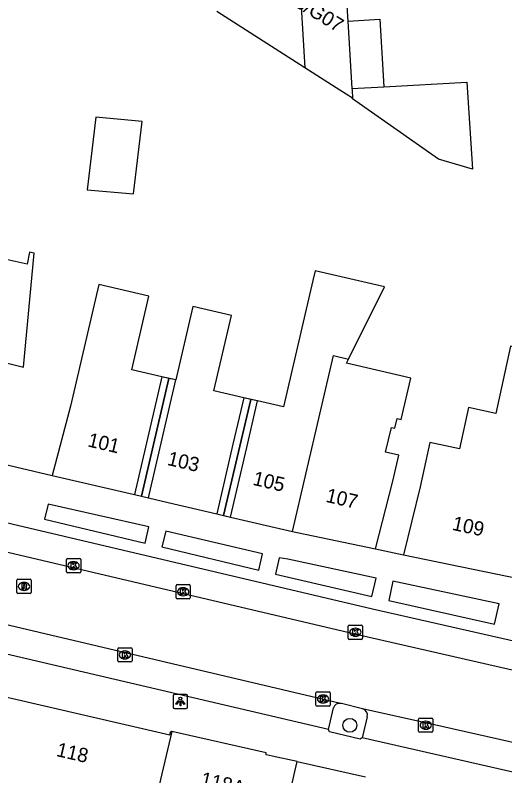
# Model space of a CAD drawing. Extents: x 159888 to 160757, y 384031 to 384746.
# Drawn here: x 160309.4 to 160343.9, y 384451.7 to 384505.3 of the extents above; entities that cross this region are included whole.
import ezdxf

# ---------------------------------------------------------------- set-up
doc = ezdxf.new("R2010")
doc.units = 0
for name, color, linetype in [('IMGEO_Boom', 7, 'Continuous'), ('IMGEO_Erf', 7, 'Continuous'), ('IMGEO_Kolk', 7, 'Continuous'), ('IMGEO_Lichtpunt', 7, 'Continuous'), ('IMGEO_Pand', 7, 'Continuous'), ('IMGEO_Pand_nummerreeks', 7, 'Continuous'), ('IMGEO_Pand_overbouw', 7, 'Continuous'), ('IMGEO_Parkeervlak_open', 7, 'Continuous'), ('IMGEO_Rijbaan_lokaal_open', 7, 'Continuous'), ('IMGEO_Rioolput', 7, 'Continuous'), ('IMGEO_Voetpad_open', 7, 'Continuous')]:
    doc.layers.add(name, color=color, linetype=linetype)

msp = doc.modelspace()

# ---------------------------------------------------------------- linework, layer by layer
at = {"layer": 'IMGEO_Boom'}
msp.add_circle((160332.99, 384455.291), 0.489, dxfattribs=at)
at = {"layer": 'IMGEO_Erf'}
for points in [[(160320.729, 384479.597), (160319.752, 384479.824)], [(160326.491, 384478.118), (160325.517, 384478.344)]]:
    msp.add_lwpolyline(points, dxfattribs=at)
at = {"layer": 'IMGEO_Kolk'}
for p, q in [((160313.032, 384466.101), (160313.032, 384466.953)), ((160313.107, 384467.027), (160313.959, 384467.027)), ((160313.52, 384466.807), (160313.545, 384466.807)), ((160314.033, 384466.953), (160314.033, 384466.101)), ((160313.959, 384466.027), (160313.107, 384466.027)), ((160313.543, 384466.247), (160313.518, 384466.247)), ((160320.751, 384464.263), (160320.751, 384465.115)), ((160320.826, 384465.189), (160321.678, 384465.189)), ((160321.239, 384464.969), (160321.264, 384464.969)), ((160321.752, 384465.115), (160321.752, 384464.263)), ((160321.262, 384464.409), (160321.237, 384464.409)), ((160321.678, 384464.189), (160320.826, 384464.189)), ((160332.876, 384461.415), (160332.876, 384462.267)), ((160332.951, 384462.341), (160333.803, 384462.341)), ((160333.877, 384462.267), (160333.877, 384461.415)), ((160333.364, 384462.121), (160333.389, 384462.121)), ((160333.803, 384461.341), (160332.951, 384461.341)), ((160333.387, 384461.561), (160333.362, 384461.561)), ((160316.649, 384459.822), (160316.649, 384460.674)), ((160316.724, 384460.748), (160317.576, 384460.748)), ((160317.65, 384460.674), (160317.65, 384459.822)), ((160317.137, 384460.528), (160317.162, 384460.528)), ((160317.576, 384459.748), (160316.724, 384459.748)), ((160317.16, 384459.968), (160317.135, 384459.968)), ((160330.601, 384456.714), (160330.601, 384457.566)), ((160330.676, 384457.64), (160331.528, 384457.64)), ((160331.602, 384457.566), (160331.602, 384456.714)), ((160331.089, 384457.42), (160331.114, 384457.42)), ((160331.528, 384456.64), (160330.676, 384456.64)), ((160331.112, 384456.86), (160331.087, 384456.86)), ((160337.832, 384454.872), (160337.832, 384455.724)), ((160337.907, 384455.798), (160338.759, 384455.798)), ((160338.32, 384455.578), (160338.345, 384455.578)), ((160338.833, 384455.724), (160338.833, 384454.872)), ((160338.759, 384454.798), (160337.907, 384454.798)), ((160338.343, 384455.018), (160338.318, 384455.018))]:
    msp.add_line(p, q, dxfattribs=at)
for points in [[(160313.032, 384466.101), (160313.032, 384466.953)], [(160313.107, 384467.027), (160313.959, 384467.027)], [(160313.353, 384466.727), (160313.476, 384466.727), (160313.476, 384466.576), (160313.606, 384466.727), (160313.77, 384466.727), (160313.624, 384466.576), (160313.777, 384466.327), (160313.625, 384466.327), (160313.54, 384466.491), (160313.476, 384466.424), (160313.476, 384466.327), (160313.353, 384466.327), (160313.353, 384466.727)], [(160314.033, 384466.953), (160314.033, 384466.101)], [(160313.959, 384466.027), (160313.107, 384466.027)], [(160320.751, 384464.263), (160320.751, 384465.115)], [(160320.826, 384465.189), (160321.678, 384465.189)], [(160321.752, 384465.115), (160321.752, 384464.263)], [(160321.072, 384464.889), (160321.195, 384464.889), (160321.195, 384464.738), (160321.325, 384464.889), (160321.489, 384464.889), (160321.343, 384464.738), (160321.496, 384464.489), (160321.344, 384464.489), (160321.259, 384464.653), (160321.195, 384464.586), (160321.195, 384464.489), (160321.072, 384464.489), (160321.072, 384464.889)], [(160321.678, 384464.189), (160320.826, 384464.189)], [(160332.876, 384461.415), (160332.876, 384462.267)], [(160332.951, 384462.341), (160333.803, 384462.341)], [(160333.877, 384462.267), (160333.877, 384461.415)], [(160333.197, 384462.041), (160333.32, 384462.041), (160333.32, 384461.89), (160333.45, 384462.041), (160333.614, 384462.041), (160333.468, 384461.89), (160333.621, 384461.641), (160333.469, 384461.641), (160333.384, 384461.805), (160333.32, 384461.738), (160333.32, 384461.641), (160333.197, 384461.641), (160333.197, 384462.041)], [(160333.803, 384461.341), (160332.951, 384461.341)], [(160316.649, 384459.822), (160316.649, 384460.674)], [(160316.724, 384460.748), (160317.576, 384460.748)], [(160317.65, 384460.674), (160317.65, 384459.822)], [(160316.97, 384460.448), (160317.093, 384460.448), (160317.093, 384460.297), (160317.223, 384460.448), (160317.387, 384460.448), (160317.241, 384460.297), (160317.394, 384460.048), (160317.242, 384460.048), (160317.157, 384460.212), (160317.093, 384460.145), (160317.093, 384460.048), (160316.97, 384460.048), (160316.97, 384460.448)], [(160317.576, 384459.748), (160316.724, 384459.748)], [(160330.601, 384456.714), (160330.601, 384457.566)], [(160330.676, 384457.64), (160331.528, 384457.64)], [(160331.602, 384457.566), (160331.602, 384456.714)], [(160330.922, 384457.34), (160331.045, 384457.34), (160331.045, 384457.189), (160331.175, 384457.34), (160331.339, 384457.34), (160331.193, 384457.189), (160331.346, 384456.94), (160331.194, 384456.94), (160331.109, 384457.104), (160331.045, 384457.037), (160331.045, 384456.94), (160330.922, 384456.94), (160330.922, 384457.34)], [(160331.528, 384456.64), (160330.676, 384456.64)], [(160337.832, 384454.872), (160337.832, 384455.724)], [(160337.907, 384455.798), (160338.759, 384455.798)], [(160338.153, 384455.498), (160338.276, 384455.498), (160338.276, 384455.347), (160338.406, 384455.498), (160338.57, 384455.498), (160338.424, 384455.347), (160338.577, 384455.098), (160338.425, 384455.098), (160338.34, 384455.262), (160338.276, 384455.195), (160338.276, 384455.098), (160338.153, 384455.098), (160338.153, 384455.498)], [(160338.833, 384455.724), (160338.833, 384454.872)], [(160338.759, 384454.798), (160337.907, 384454.798)]]:
    msp.add_lwpolyline(points, dxfattribs=at)
for centre, start, end in [((160313.109, 384466.951), 91.552, 178.448), ((160313.109, 384466.951), 91.552, 178.448), ((160313.957, 384466.951), 1.552, 88.448), ((160313.957, 384466.951), 1.552, 88.448), ((160313.109, 384466.103), 181.552, 268.448), ((160313.109, 384466.103), 181.552, 268.448), ((160313.957, 384466.103), 271.552, 358.448), ((160313.957, 384466.103), 271.552, 358.448), ((160320.828, 384465.113), 91.552, 178.448), ((160320.828, 384465.113), 91.552, 178.448), ((160321.676, 384465.113), 1.552, 88.448), ((160321.676, 384465.113), 1.552, 88.448), ((160320.828, 384464.265), 181.552, 268.448), ((160320.828, 384464.265), 181.552, 268.448), ((160321.676, 384464.265), 271.552, 358.448), ((160321.676, 384464.265), 271.552, 358.448), ((160332.953, 384462.265), 91.552, 178.448), ((160332.953, 384462.265), 91.552, 178.448), ((160333.801, 384462.265), 1.552, 88.448), ((160333.801, 384462.265), 1.552, 88.448), ((160332.953, 384461.417), 181.552, 268.448), ((160332.953, 384461.417), 181.552, 268.448), ((160333.801, 384461.417), 271.552, 358.448), ((160333.801, 384461.417), 271.552, 358.448), ((160316.726, 384460.672), 91.552, 178.448), ((160316.726, 384460.672), 91.552, 178.448), ((160317.574, 384460.672), 1.552, 88.448), ((160317.574, 384460.672), 1.552, 88.448), ((160316.726, 384459.824), 181.552, 268.448), ((160316.726, 384459.824), 181.552, 268.448), ((160317.574, 384459.824), 271.552, 358.448), ((160317.574, 384459.824), 271.552, 358.448), ((160330.678, 384457.564), 91.552, 178.448), ((160330.678, 384457.564), 91.552, 178.448), ((160331.526, 384457.564), 1.552, 88.448), ((160331.526, 384457.564), 1.552, 88.448), ((160330.678, 384456.716), 181.552, 268.448), ((160330.678, 384456.716), 181.552, 268.448), ((160331.526, 384456.716), 271.552, 358.448), ((160331.526, 384456.716), 271.552, 358.448), ((160337.909, 384455.722), 91.552, 178.448), ((160337.909, 384455.722), 91.552, 178.448), ((160338.757, 384455.722), 1.552, 88.448), ((160338.757, 384455.722), 1.552, 88.448), ((160337.909, 384454.874), 181.552, 268.448), ((160337.909, 384454.874), 181.552, 268.448), ((160338.757, 384454.874), 271.552, 358.448), ((160338.757, 384454.874), 271.552, 358.448)]:
    msp.add_arc(centre, 0.0765, start, end, dxfattribs=at)
for centre, major_axis, ratio, start_param, end_param in [((160313.519, 384466.527), (-0.387, 0.002), 0.722429, 4.712389, 7.853982), ((160313.544, 384466.527), (-0.39, 0.002), 0.717154, 1.570796, 4.712389), ((160321.238, 384464.689), (-0.387, 0.002), 0.722429, 4.712389, 7.853982), ((160321.263, 384464.689), (-0.39, 0.002), 0.717154, 1.570796, 4.712389), ((160333.363, 384461.841), (-0.387, 0.002), 0.722429, 4.712389, 7.853982), ((160333.388, 384461.841), (-0.39, 0.002), 0.717154, 1.570796, 4.712389), ((160317.136, 384460.248), (-0.387, 0.002), 0.722429, 4.712389, 7.853982), ((160317.161, 384460.248), (-0.39, 0.002), 0.717154, 1.570796, 4.712389), ((160331.088, 384457.14), (-0.387, 0.002), 0.722429, 4.712389, 7.853982), ((160331.113, 384457.14), (-0.39, 0.002), 0.717154, 1.570796, 4.712389), ((160338.319, 384455.298), (-0.387, 0.002), 0.722429, 4.712389, 7.853982), ((160338.344, 384455.298), (-0.39, 0.002), 0.717154, 1.570796, 4.712389)]:
    msp.add_ellipse(centre, major_axis=major_axis, ratio=ratio, start_param=start_param, end_param=end_param, dxfattribs=at)
at = {"layer": 'IMGEO_Lichtpunt'}
for p, q in [((160321.456, 384457.468), (160320.648, 384457.468)), ((160321.456, 384457.468), (160320.648, 384457.468)), ((160320.554, 384457.373), (160320.554, 384456.566)), ((160320.554, 384457.373), (160320.554, 384456.566)), ((160321.55, 384456.566), (160321.55, 384457.373)), ((160321.55, 384456.566), (160321.55, 384457.373)), ((160320.648, 384456.472), (160321.456, 384456.472)), ((160320.648, 384456.472), (160321.456, 384456.472))]:
    msp.add_line(p, q, dxfattribs=at)
for points in [[(160320.928, 384457.037), (160320.967, 384457.009), (160320.779, 384456.747), (160320.741, 384456.774), (160320.928, 384457.037)], [(160321.03, 384456.989), (160321.077, 384456.989), (160321.077, 384456.667), (160321.03, 384456.667), (160321.03, 384456.989)], [(160321.14, 384457.009), (160321.178, 384457.036), (160321.365, 384456.774), (160321.326, 384456.746), (160321.14, 384457.009)]]:
    msp.add_lwpolyline(points, dxfattribs=at)
msp.add_circle((160321.053, 384457.171), 0.0994, dxfattribs=at)
for centre, start, end in [((160320.648, 384457.373), 90, 180), ((160320.648, 384457.373), 90, 180), ((160321.456, 384457.373), 0, 90), ((160321.456, 384457.373), 0, 90), ((160320.648, 384456.566), 180, 270), ((160320.648, 384456.566), 180, 270), ((160321.456, 384456.566), 270, 0), ((160321.456, 384456.566), 270, 360)]:
    msp.add_arc(centre, 0.0946, start, end, dxfattribs=at)
at = {"layer": 'IMGEO_Pand'}
for points in [[(160332.338, 384512.734), (160332.835, 384504.845)], [(160329.154, 384512.544), (160329.809, 384501.573)], [(160329.809, 384501.573), (160323.63, 384505.519)], [(160332.835, 384504.845), (160335.088, 384504.987), (160335.387, 384500.238)], [(160332.835, 384504.845), (160333.134, 384500.117)], [(160333.177, 384499.422), (160332.272, 384500), (160329.809, 384501.573)], [(160335.387, 384500.238), (160341.231, 384500.551), (160341.618, 384494.423), (160339.232, 384495.137), (160333.181, 384499.372), (160333.177, 384499.422)], [(160333.134, 384500.117), (160335.387, 384500.238)], [(160333.134, 384500.117), (160333.141, 384500), (160333.177, 384499.422)], [(160314.495, 384492.979), (160317.753, 384492.687), (160318.362, 384497.794), (160315.104, 384498.086), (160314.495, 384492.979)], [(160300.376, 384475.627), (160301.922, 384482.541), (160304.86, 384481.798), (160310.003, 384480.497), (160310.763, 384488.511), (160310.439, 384488.584), (160310.255, 384487.749), (160306.005, 384488.688), (160306.028, 384488.791), (160305.806, 384488.84), (160305.758, 384488.618), (160305.418, 384485.426), (160299.862, 384486.699), (160302.098, 384496.447), (160299.125, 384497.128), (160294.547, 384477.036)], [(160332.887, 384481.062), (160335.419, 384486.146), (160330.547, 384487.279), (160330.389, 384486.6), (160328.317, 384477.693), (160326.491, 384478.118)], [(160348.55, 384482.581), (160349.26, 384485.901), (160346.381, 384486.526), (160345.342, 384481.739), (160344.295, 384481.966), (160343.27, 384477.243), (160341.352, 384477.659), (160340.719, 384474.745), (160338.631, 384475.199), (160337.951, 384472.067), (160336.774, 384467.292)], [(160319.752, 384479.824), (160317.628, 384480.319), (160318.834, 384485.503), (160315.31, 384486.323), (160313.313, 384477.742), (160312.033, 384472.883)], [(160325.517, 384478.344), (160323.42, 384478.832), (160324.651, 384484.122), (160321.929, 384484.755), (160320.729, 384479.597)], [(160328.957, 384468.924), (160331.842, 384481.306), (160332.887, 384481.062)], [(160334.796, 384467.707), (160336.011, 384472.462), (160336.438, 384474.298), (160335.506, 384474.514), (160335.911, 384476.256), (160336.162, 384476.197), (160336.321, 384476.882), (160336.605, 384476.816), (160337.279, 384479.713), (160332.741, 384480.769), (160332.887, 384481.062)], [(160319.752, 384479.824), (160317.826, 384471.523)], [(160318.799, 384471.294), (160320.729, 384479.597)], [(160325.517, 384478.344), (160324.758, 384475.08), (160323.615, 384470.169)], [(160324.589, 384469.942), (160325.732, 384474.854), (160326.491, 384478.118)], [(160312.033, 384472.883), (160317.826, 384471.523)], [(160318.799, 384471.294), (160320.202, 384470.965), (160323.615, 384470.169)], [(160324.589, 384469.942), (160328.957, 384468.924)], [(160328.957, 384468.924), (160329.273, 384468.85), (160334.796, 384467.707)], [(160336.774, 384467.292), (160344.87, 384465.614)], [(160308.014, 384457.469), (160308.654, 384457.315), (160320.317, 384454.624), (160320.372, 384454.868), (160320.454, 384454.849)], [(160320.454, 384454.849), (160318.547, 384446.811), (160327.398, 384444.569)], [(160329.279, 384452.738), (160327.527, 384453.125), (160327.088, 384453.222), (160327.104, 384453.346), (160320.454, 384454.849)], [(160327.398, 384444.569), (160329.279, 384452.738)], [(160329.279, 384452.738), (160334.09, 384451.675)]]:
    msp.add_lwpolyline(points, dxfattribs=at)
at = {"layer": 'IMGEO_Pand_overbouw'}
for points in [[(160320.242, 384479.71), (160319.752, 384479.824), (160317.826, 384471.523), (160318.313, 384471.409)], [(160320.729, 384479.597), (160320.242, 384479.71), (160318.313, 384471.409), (160318.799, 384471.294)], [(160326.004, 384478.231), (160325.517, 384478.344), (160324.758, 384475.08), (160323.615, 384470.169), (160324.102, 384470.056)], [(160325.732, 384474.854), (160326.491, 384478.118), (160326.004, 384478.231), (160324.102, 384470.056), (160324.589, 384469.942)]]:
    msp.add_lwpolyline(points, close=True, dxfattribs=at)
at = {"layer": 'IMGEO_Parkeervlak_open'}
for points in [[(160331.476, 384454.994), (160331.838, 384456.514)], [(160334.216, 384455.884), (160333.85, 384454.4)]]:
    msp.add_lwpolyline(points, dxfattribs=at)
for centre, radius, start, end in [((160332.264, 384456.399), 0.441, 80.692, 164.86), ((160333.755, 384456), 0.476, 345.883, 74.7166)]:
    msp.add_arc(centre, radius, start, end, dxfattribs=at)
at = {"layer": 'IMGEO_Rijbaan_lokaal_open'}
for points in [[(160282.941, 384473.571), (160333.744, 384461.627), (160349.856, 384457.953)], [(160332.335, 384456.834), (160302.52, 384463.845)], [(160333.88, 384456.459), (160332.396, 384456.82), (160332.335, 384456.834)], [(160349.763, 384452.894), (160339.475, 384455.203), (160333.88, 384456.459)]]:
    msp.add_lwpolyline(points, dxfattribs=at)
at = {"layer": 'IMGEO_Rioolput'}
for p, q in [((160309.543, 384464.643), (160309.543, 384465.495)), ((160309.618, 384465.569), (160310.47, 384465.569)), ((160310.544, 384465.495), (160310.544, 384464.643)), ((160310.031, 384465.349), (160310.056, 384465.349)), ((160310.47, 384464.569), (160309.618, 384464.569)), ((160310.054, 384464.789), (160310.029, 384464.789))]:
    msp.add_line(p, q, dxfattribs=at)
for points in [[(160309.543, 384464.643), (160309.543, 384465.495)], [(160309.618, 384465.569), (160310.47, 384465.569)], [(160310.544, 384465.495), (160310.544, 384464.643)], [(160310.132, 384465.267), (160309.88, 384465.269), (160309.88, 384464.869)], [(160309.88, 384464.869), (160310.004, 384464.869), (160310.004, 384465.031), (160310.015, 384465.031)], [(160310.058, 384465.188), (160310.004, 384465.188), (160310.004, 384465.107)], [(160310.004, 384465.107), (160310.056, 384465.107)], [(160310.062, 384465.002), (160310.133, 384464.869), (160310.273, 384464.869), (160310.208, 384464.995)], [(160310.47, 384464.569), (160309.618, 384464.569)]]:
    msp.add_lwpolyline(points, dxfattribs=at)
for centre, radius, start, end in [((160309.62, 384465.493), 0.0765, 91.552, 178.448), ((160309.62, 384465.493), 0.0765, 91.552, 178.448), ((160310.468, 384465.493), 0.0765, 1.552, 88.448), ((160310.468, 384465.493), 0.0765, 1.552, 88.448), ((160310.014, 384464.978), 0.0533, 26.0293, 88.6989), ((160310.04, 384465.296), 0.19, 274.7715, 282.9687), ((160310.064, 384465.092), 0.0964, 77.0061, 93.1865), ((160310.078, 384465.149), 0.0378, 276.6634, 79.6772), ((160310.131, 384465.157), 0.109, 350.3612, 89.416), ((160310.129, 384465.157), 0.112, 277.5842, 350.9817), ((160310.113, 384464.942), 0.108, 29.5134, 73.7905), ((160309.62, 384464.645), 0.0765, 181.552, 268.448), ((160309.62, 384464.645), 0.0765, 181.552, 268.448), ((160310.468, 384464.645), 0.0765, 271.552, 358.448), ((160310.468, 384464.645), 0.0765, 271.552, 358.448)]:
    msp.add_arc(centre, radius, start, end, dxfattribs=at)
for centre, major_axis, ratio, start_param, end_param in [((160310.03, 384465.069), (-0.387, 0.002), 0.722429, 4.712389, 7.853982), ((160310.055, 384465.069), (-0.39, 0.002), 0.717154, 1.570796, 4.712389)]:
    msp.add_ellipse(centre, major_axis=major_axis, ratio=ratio, start_param=start_param, end_param=end_param, dxfattribs=at)
at = {"layer": 'IMGEO_Voetpad_open'}
for points in [[(160349.788, 384460.02), (160334.593, 384463.468), (160283.766, 384475.429)], [(160300.376, 384475.627), (160312.033, 384472.883)], [(160317.826, 384471.523), (160318.799, 384471.294)], [(160311.743, 384470.856), (160311.477, 384469.795), (160318.572, 384468.117), (160318.841, 384469.248), (160311.743, 384470.856)], [(160323.615, 384470.169), (160324.589, 384469.942)], [(160320.023, 384468.952), (160319.751, 384467.847), (160326.581, 384466.219), (160326.837, 384467.356), (160320.023, 384468.952)], [(160334.796, 384467.707), (160336.774, 384467.292)], [(160328.015, 384467.084), (160327.746, 384465.934), (160334.547, 384464.349), (160334.83, 384465.644), (160328.627, 384466.972), (160328.015, 384467.084)], [(160336.016, 384465.438), (160335.725, 384464.072), (160343.179, 384462.399), (160343.502, 384463.85), (160336.016, 384465.438)], [(160331.476, 384454.994), (160302.477, 384461.784)], [(160333.85, 384454.4), (160333.717, 384454.32), (160331.563, 384454.821), (160331.476, 384454.994)], [(160357.759, 384448.977), (160333.85, 384454.4)]]:
    msp.add_lwpolyline(points, dxfattribs=at)

# ---------------------------------------------------------------- texts
at = {"layer": 'IMGEO_Pand_nummerreeks'}
for s, rotation, p in [('98/G07', 328.5217, (160328.405, 384506.314)), ('101', 346.9079, (160314.47, 384474.927)), ('103', 346.9079, (160320.081, 384473.622)), ('105', 346.9079, (160326.1, 384472.223)), ('107', 346.8965, (160331.24, 384471.026)), ('109', 347.7559, (160340.14, 384469.054)), ('118', 347.0683, (160312.263, 384453.133)), ('118A', 347.1486, (160322.415, 384451.058))]:
    msp.add_text(s, height=1, rotation=rotation, dxfattribs=at).set_placement(p)

doc.saveas('drawing.dxf')
